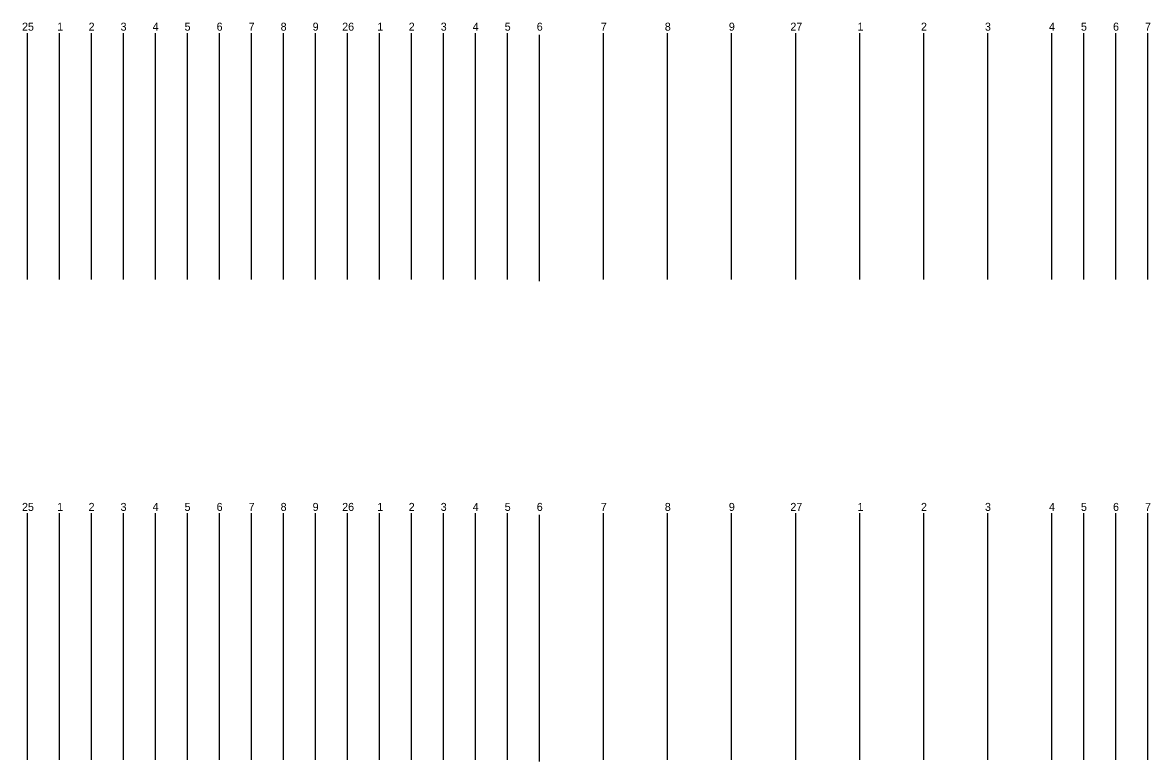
# Model space of a CAD drawing. Extents: x 2343 to 7744, y -5890 to 2050.
# Drawn here: x 5717 to 6422, y -5455 to -4993 of the extents above; entities that cross this region are included whole.
import ezdxf

# ---------------------------------------------------------------- set-up
doc = ezdxf.new("R2010")
doc.units = 0
doc.layers.add('Vrstva 1', color=7, linetype='Continuous')

msp = doc.modelspace()

# ---------------------------------------------------------------- linework, layer by layer
for p, q in [((5720, -5000), (5720, -5154)), ((5740, -5000), (5740, -5154)), ((5760, -5000), (5760, -5154)), ((5780, -5000), (5780, -5154)), ((5800, -5000), (5800, -5154)), ((5800, -5000), (5800, -5154)), ((5820, -5000), (5820, -5154)), ((5840, -5000), (5840, -5154)), ((5860, -5000), (5860, -5154)), ((5880, -5000), (5880, -5154)), ((5900, -5000), (5900, -5154)), ((5920, -5000), (5920, -5154)), ((5940, -5000), (5940, -5154)), ((5960, -5000), (5960, -5154)), ((5980, -5000), (5980, -5154)), ((6000, -5000), (6000, -5154)), ((6020, -5000), (6020, -5154)), ((6040, -5001), (6040, -5155)), ((6080, -5000), (6080, -5154)), ((6120, -5000), (6120, -5154)), ((6160, -5000), (6160, -5154)), ((6200, -5000), (6200, -5154)), ((6240, -5000), (6240, -5154)), ((6280, -5000), (6280, -5154)), ((6320, -5000), (6320, -5154)), ((6360, -5000), (6360, -5154)), ((6380, -5000), (6380, -5154)), ((6400, -5000), (6400, -5154)), ((6420, -5000), (6420, -5154)), ((5720, -5300), (5720, -5454)), ((5740, -5300), (5740, -5454)), ((5760, -5300), (5760, -5454)), ((5780, -5300), (5780, -5454)), ((5800, -5300), (5800, -5454)), ((5800, -5300), (5800, -5454)), ((5820, -5300), (5820, -5454)), ((5840, -5300), (5840, -5454)), ((5860, -5300), (5860, -5454)), ((5880, -5300), (5880, -5454)), ((5900, -5300), (5900, -5454)), ((5920, -5300), (5920, -5454)), ((5940, -5300), (5940, -5454)), ((5960, -5300), (5960, -5454)), ((5980, -5300), (5980, -5454)), ((6000, -5300), (6000, -5454)), ((6020, -5300), (6020, -5454)), ((6040, -5301), (6040, -5455)), ((6080, -5300), (6080, -5454)), ((6120, -5300), (6120, -5454)), ((6160, -5300), (6160, -5454)), ((6200, -5300), (6200, -5454)), ((6240, -5300), (6240, -5454)), ((6280, -5300), (6280, -5454)), ((6320, -5300), (6320, -5454)), ((6360, -5300), (6360, -5454)), ((6380, -5300), (6380, -5454)), ((6400, -5300), (6400, -5454)), ((6420, -5300), (6420, -5454))]:
    msp.add_line(p, q)

# ---------------------------------------------------------------- texts
at = {"layer": 'Vrstva 1'}
for s, p in [('25', (5716.88, -4998.5)), ('1', (5738.84, -4998.5)), ('2', (5758.47, -4998.5)), ('3', (5778.45, -4998.5)), ('4', (5798.46, -4998.5)), ('5', (5818.43, -4998.5)), ('6', (5838.45, -4998.5)), ('7', (5858.45, -4998.5)), ('8', (5878.45, -4998.5)), ('9', (5898.45, -4998.5)), ('26', (5916.89, -4998.5)), ('1', (5938.84, -4998.5)), ('2', (5958.47, -4998.5)), ('3', (5978.45, -4998.5)), ('4', (5998.46, -4998.5)), ('5', (6018.43, -4998.5)), ('6', (6038.45, -4998.5)), ('7', (6078.45, -4998.5)), ('8', (6118.45, -4998.5)), ('9', (6158.45, -4998.5)), ('27', (6196.89, -4998.5)), ('1', (6238.84, -4998.5)), ('2', (6278.47, -4998.5)), ('3', (6318.45, -4998.5)), ('4', (6358.46, -4998.5)), ('5', (6378.43, -4998.5)), ('6', (6398.45, -4998.5)), ('7', (6418.45, -4998.5)), ('25', (5716.88, -5298.5)), ('1', (5738.84, -5298.5)), ('2', (5758.47, -5298.5)), ('3', (5778.45, -5298.5)), ('4', (5798.46, -5298.5)), ('5', (5818.43, -5298.5)), ('6', (5838.45, -5298.5)), ('7', (5858.45, -5298.5)), ('8', (5878.45, -5298.5)), ('9', (5898.45, -5298.5)), ('26', (5916.89, -5298.5)), ('1', (5938.84, -5298.5)), ('2', (5958.47, -5298.5)), ('3', (5978.45, -5298.5)), ('4', (5998.46, -5298.5)), ('5', (6018.43, -5298.5)), ('6', (6038.45, -5298.5)), ('7', (6078.45, -5298.5)), ('8', (6118.45, -5298.5)), ('9', (6158.45, -5298.5)), ('27', (6196.89, -5298.5)), ('1', (6238.84, -5298.5)), ('2', (6278.47, -5298.5)), ('3', (6318.45, -5298.5)), ('4', (6358.46, -5298.5)), ('5', (6378.43, -5298.5)), ('6', (6398.45, -5298.5)), ('7', (6418.45, -5298.5))]:
    msp.add_text(s, height=5, dxfattribs=at).set_placement(p)

doc.saveas('drawing.dxf')
